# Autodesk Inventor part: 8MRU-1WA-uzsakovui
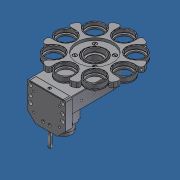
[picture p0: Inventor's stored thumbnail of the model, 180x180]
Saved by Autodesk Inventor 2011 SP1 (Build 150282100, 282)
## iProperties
Created: 2012-07
Part Number: 8MRU-1WA-uzsakovui
Document SubType Name: Modeling
Designer: a
Density: 1 g/cm^3
Author: a
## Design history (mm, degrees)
feature "Base1"
body "Solid1"
